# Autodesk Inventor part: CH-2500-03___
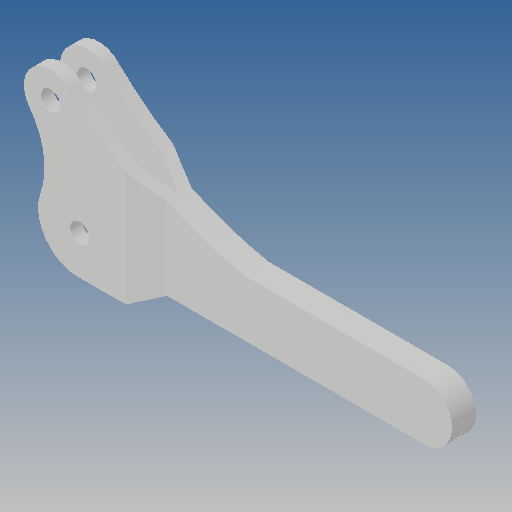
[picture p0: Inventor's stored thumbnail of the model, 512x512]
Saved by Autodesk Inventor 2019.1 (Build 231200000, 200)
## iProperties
Created: 2012-09
Part Number: CH-2500-03___
Material: Ogólny
Document SubType Name: Modeling
Designer: CADENGINEERING4
Density: 1 g/cm^3
Appearance: Domyślna
Author: CADENGINEERING4
Revision Number: ÈÎºÎ
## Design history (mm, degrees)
feature "NONE" [ÊäÈë]
feature "ÊäÈë2"
node "Bryła1"
node "Bryła2"
